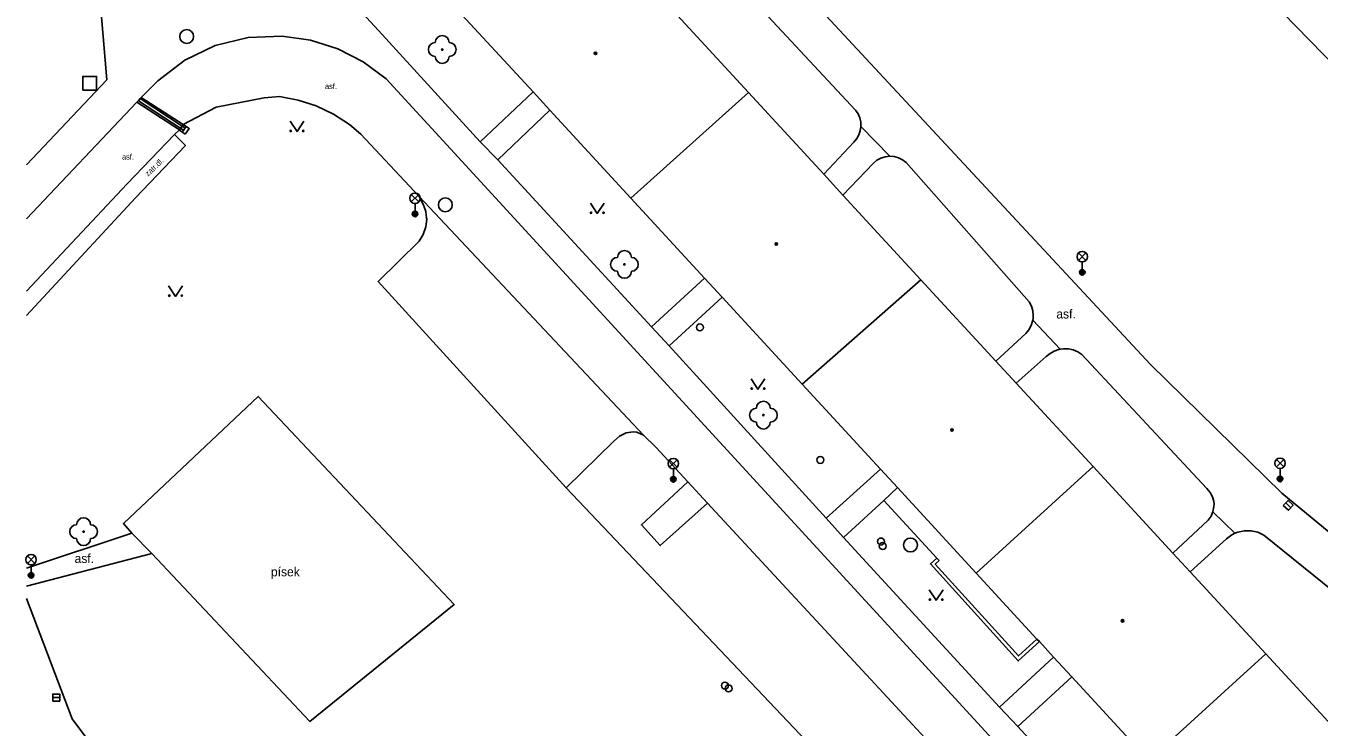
# Model space of a CAD drawing. Extents: x -598932 to -598196, y -1162207 to -1161504.
# Drawn here: x -598932.1 to -598839, y -1161892.2 to -1161841.7 of the extents above; entities that cross this region are included whole.
import ezdxf

# ---------------------------------------------------------------- set-up
doc = ezdxf.new("R2010")
doc.units = 0
for name, color, linetype in [('kanalizace - povrch.  znaky - skut. velikost', 7, 'Continuous'), ('Level 22', 7, 'Continuous'), ('Level 26', 7, 'Continuous'), ('Level 27', 7, 'Continuous'), ('Level 28', 7, 'Continuous'), ('Level 33', 7, 'Continuous'), ('Level 36', 7, 'Continuous'), ('Level 39', 7, 'Continuous'), ('specificka linie pasportu komunikaci', 7, 'Continuous'), ('TM - budovy zdene_ betonove - VP', 7, 'Continuous'), ('TM - chodniky - VP', 7, 'Continuous'), ('TM - komunikace - VP', 7, 'Continuous'), ('TM - letecke snimky - pomocna linie', 7, 'Continuous'), ('TM - popis povrchu', 7, 'Continuous'), ('TM - rozhrani mezi zpev. plochami mezi sebou - VP', 7, 'Continuous'), ('TM - rozhrani ploch obecne - VP', 7, 'Continuous')]:
    doc.layers.add(name, color=color, linetype=linetype)

msp = doc.modelspace()

# ---------------------------------------------------------------- linework, layer by layer
at = {"layer": 'kanalizace - povrch.  znaky - skut. velikost'}
for points in [[(-598923.95, -1161847.12), (-598923.84, -1161846.95)], [(-598920.92, -1161849.1), (-598923.95, -1161847.12)], [(-598920.81, -1161848.93), (-598923.84, -1161846.95)], [(-598920.72, -1161849.23), (-598920.92, -1161849.1)], [(-598920.61, -1161849.06), (-598920.81, -1161848.93)], [(-598920.72, -1161849.23), (-598920.61, -1161849.06)]]:
    msp.add_lwpolyline(points, dxfattribs=at)
at = {"layer": 'Level 22'}
for centre in [(-598902.1, -1161843.43), (-598888.99, -1161858.88), (-598878.99, -1161869.72), (-598927.91, -1161878.1)]:
    msp.add_circle(centre, 0.05, dxfattribs=at)
for centre, start, end in [((-598902.6, -1161843.43), 90, 270), ((-598902.1, -1161842.93), 0, 180), ((-598901.6, -1161843.43), 270, 90), ((-598902.1, -1161843.93), 180, 0), ((-598888.99, -1161858.38), 0, 180), ((-598889.49, -1161858.88), 90, 270), ((-598888.49, -1161858.88), 270, 90), ((-598888.99, -1161859.38), 180, 0), ((-598878.99, -1161869.22), 0, 180), ((-598879.49, -1161869.72), 90, 270), ((-598878.49, -1161869.72), 270, 90), ((-598878.99, -1161870.22), 180, 0), ((-598927.91, -1161877.6), 0, 180), ((-598928.41, -1161878.1), 90, 270), ((-598927.41, -1161878.1), 270, 90), ((-598927.91, -1161878.6), 180, 0)]:
    msp.add_arc(centre, 0.5, start, end, dxfattribs=at)
at = {"layer": 'Level 26'}
msp.add_lwpolyline([(-598927.97, -1161846.36), (-598926.97, -1161846.36), (-598926.97, -1161845.36), (-598927.97, -1161845.36)], close=True, dxfattribs=at)
at = {"layer": 'Level 27'}
for p, q in [((-598920.813, -1161849.375), (-598920.527, -1161848.965)), ((-598841.401, -1161876.038), (-598841.038, -1161876.382)), ((-598930.13, -1161890.03), (-598929.63, -1161890.03))]:
    msp.add_line(p, q, dxfattribs=at)
for points in [[(-598920.607, -1161849.518), (-598920.322, -1161849.107), (-598920.733, -1161848.822), (-598921.018, -1161849.233)], [(-598841.573, -1161876.22), (-598841.21, -1161876.563), (-598840.866, -1161876.2), (-598841.229, -1161875.857)], [(-598930.13, -1161890.28), (-598929.63, -1161890.28), (-598929.63, -1161889.78), (-598930.13, -1161889.78)]]:
    msp.add_lwpolyline(points, close=True, dxfattribs=at)
for centre in [(-598920.49, -1161842.49), (-598901.88, -1161854.6), (-598868.4, -1161879.06)]:
    msp.add_circle(centre, 0.5, dxfattribs=at)
at = {"layer": 'Level 28'}
for centre in [(-598883.56, -1161863.41), (-598874.89, -1161872.94), (-598870.53, -1161878.81), (-598870.4, -1161879.14), (-598881.76, -1161889.17), (-598881.49, -1161889.37)]:
    msp.add_circle(centre, 0.25, dxfattribs=at)
at = {"layer": 'Level 33'}
for p, q in [((-598904.325, -1161854.39), (-598903.795, -1161853.86)), ((-598904.325, -1161853.86), (-598903.795, -1161854.39)), ((-598904.06, -1161854.5), (-598904.06, -1161855.25)), ((-598856.305, -1161858.59), (-598855.775, -1161858.06)), ((-598856.305, -1161858.06), (-598855.775, -1161858.59)), ((-598856.04, -1161858.7), (-598856.04, -1161859.45)), ((-598885.735, -1161873.47), (-598885.205, -1161872.94)), ((-598885.735, -1161872.94), (-598885.205, -1161873.47)), ((-598885.47, -1161873.58), (-598885.47, -1161874.33)), ((-598842.075, -1161873.45), (-598841.545, -1161872.92)), ((-598842.075, -1161872.92), (-598841.545, -1161873.45)), ((-598841.81, -1161873.56), (-598841.81, -1161874.31)), ((-598931.955, -1161880.38), (-598931.425, -1161879.85)), ((-598931.955, -1161879.85), (-598931.425, -1161880.38)), ((-598931.69, -1161880.49), (-598931.69, -1161881.24))]:
    msp.add_line(p, q, dxfattribs=at)
for centre, radius in [((-598904.06, -1161854.125), 0.375), ((-598904.06, -1161855.25), 0.2), ((-598904.06, -1161855.25), 0.145), ((-598904.06, -1161855.25), 0.0876), ((-598856.04, -1161858.325), 0.375), ((-598856.04, -1161859.45), 0.2), ((-598856.04, -1161859.45), 0.145), ((-598856.04, -1161859.45), 0.0876), ((-598885.47, -1161873.205), 0.375), ((-598841.81, -1161873.185), 0.375), ((-598885.47, -1161874.33), 0.2), ((-598885.47, -1161874.33), 0.145), ((-598885.47, -1161874.33), 0.0876), ((-598841.81, -1161874.31), 0.2), ((-598841.81, -1161874.31), 0.145), ((-598841.81, -1161874.31), 0.0876), ((-598931.69, -1161880.115), 0.375), ((-598931.69, -1161881.24), 0.2), ((-598931.69, -1161881.24), 0.145), ((-598931.69, -1161881.24), 0.0876)]:
    msp.add_circle(centre, radius, dxfattribs=at)
at = {"layer": 'Level 36'}
for points in [[(-598913.05, -1161848.58), (-598912.55, -1161849.33), (-598912.05, -1161848.58)], [(-598891.44, -1161854.47), (-598890.94, -1161855.22), (-598890.44, -1161854.47)], [(-598921.79, -1161860.43), (-598921.29, -1161861.18), (-598920.79, -1161860.43)], [(-598879.88, -1161867.11), (-598879.38, -1161867.86), (-598878.88, -1161867.11)], [(-598867.06, -1161882.28), (-598866.56, -1161883.03), (-598866.06, -1161882.28)]]:
    msp.add_lwpolyline(points, dxfattribs=at)
for centre in [(-598913, -1161849.28), (-598912.101, -1161849.28), (-598891.39, -1161855.17), (-598890.491, -1161855.17), (-598921.74, -1161861.13), (-598920.841, -1161861.13), (-598879.83, -1161867.81), (-598878.931, -1161867.81), (-598867.01, -1161882.98), (-598866.111, -1161882.98)]:
    msp.add_circle(centre, 0.05, dxfattribs=at)
at = {"layer": 'Level 39'}
for centre, radius in [((-598891.07, -1161843.7), 0.09), ((-598891.07, -1161843.7), 0.0398), ((-598878.06, -1161857.42), 0.09), ((-598878.06, -1161857.42), 0.0398), ((-598865.42, -1161870.79), 0.09), ((-598865.42, -1161870.79), 0.0398), ((-598853.14, -1161884.51), 0.09), ((-598853.14, -1161884.51), 0.0398)]:
    msp.add_circle(centre, radius, dxfattribs=at)
at = {"layer": 'specificka linie pasportu komunikaci'}
for points in [[(-598869.9, -1161851.1), (-598871.97, -1161848.96)], [(-598899.36, -1161850.06), (-598898.1, -1161851.36)], [(-598887.61, -1161871.17), (-598903.77, -1161854.01)], [(-598887.03, -1161863.37), (-598885.76, -1161864.74)], [(-598857.616, -1161864.984), (-598857.62, -1161864.98), (-598859.598, -1161862.898)], [(-598883, -1161876.05), (-598886.413, -1161879.096), (-598887.768, -1161877.618), (-598884.42, -1161874.52)], [(-598870.33, -1161875.86), (-598869.33, -1161874.93)], [(-598874.47, -1161877.13), (-598873.22, -1161878.51)], [(-598845.05, -1161878.22), (-598846.64, -1161876.68)], [(-598862, -1161890.72), (-598860.69, -1161892.12)]]:
    msp.add_lwpolyline(points, dxfattribs=at)
at = {"layer": 'TM - budovy zdene_ betonove - VP'}
for points in [[(-598895.56, -1161846.48), (-598901.28, -1161840.28)], [(-598885.74, -1161840.37), (-598880.07, -1161846.52)], [(-598894.35, -1161847.8), (-598895.56, -1161846.48)], [(-598888.53, -1161854.11), (-598880.07, -1161846.52)], [(-598880.07, -1161846.52), (-598874.64, -1161852.4)], [(-598888.53, -1161854.11), (-598894.35, -1161847.8)], [(-598874.64, -1161852.4), (-598873.26, -1161853.9)], [(-598883.23, -1161859.86), (-598888.53, -1161854.11)], [(-598873.26, -1161853.9), (-598867.66, -1161859.98)], [(-598881.96, -1161861.24), (-598883.23, -1161859.86)], [(-598876.19, -1161867.5), (-598867.66, -1161859.98)], [(-598867.66, -1161859.98), (-598862.26, -1161865.83)], [(-598876.19, -1161867.5), (-598881.96, -1161861.24)], [(-598862.26, -1161865.83), (-598860.8, -1161867.42)], [(-598870.55, -1161873.61), (-598876.19, -1161867.5)], [(-598860.8, -1161867.42), (-598855.26, -1161873.42)], [(-598863.67, -1161881.08), (-598869.33, -1161874.93), (-598870.55, -1161873.61)], [(-598863.67, -1161881.08), (-598855.26, -1161873.42)], [(-598855.26, -1161873.42), (-598849.52, -1161879.64)], [(-598849.52, -1161879.64), (-598848.28, -1161880.99)], [(-598859.3, -1161885.82), (-598863.67, -1161881.08)], [(-598848.28, -1161880.99), (-598842.84, -1161886.89)], [(-598859.13, -1161886), (-598859.3, -1161885.82)], [(-598858.1, -1161887.12), (-598859.13, -1161886)], [(-598856.8, -1161888.53), (-598858.1, -1161887.12)], [(-598844.96, -1161888.82), (-598842.84, -1161886.89)], [(-598842.84, -1161886.89), (-598837.25, -1161892.95)], [(-598851.24, -1161894.56), (-598856.8, -1161888.53)], [(-598844.96, -1161888.82), (-598851.24, -1161894.56)]]:
    msp.add_lwpolyline(points, dxfattribs=at)
at = {"layer": 'TM - chodniky - VP'}
for points in [[(-598867.84, -1161813.9), (-598809.56, -1161873.6), (-598820.89, -1161890.44), (-598832.15, -1161883.16), (-598841.68, -1161875.32), (-598851.13, -1161866.08), (-598878.95, -1161836.17), (-598885.26, -1161828.7), (-598885.4, -1161826.42), (-598876.78, -1161822.62), (-598867.84, -1161813.9)], [(-598899.36, -1161850.06), (-598906.43, -1161842.36), (-598911.98, -1161836.28)], [(-598872.35, -1161847.79), (-598880.98, -1161838.53)], [(-598926.24, -1161845.61), (-598926.62, -1161841.08)], [(-598932.017, -1161851.717), (-598926.24, -1161845.61)], [(-598895.56, -1161846.48), (-598899.36, -1161850.06)], [(-598894.35, -1161847.8), (-598898.1, -1161851.36), (-598887.03, -1161863.37), (-598883.23, -1161859.86)], [(-598872.35, -1161847.79), (-598872.176, -1161848.051), (-598872.052, -1161848.339), (-598871.982, -1161848.645), (-598871.97, -1161848.96), (-598872.015, -1161849.269), (-598872.116, -1161849.565), (-598872.269, -1161849.839), (-598872.47, -1161850.08)], [(-598921.37, -1161849.55), (-598920.58, -1161850.33), (-598924.17, -1161854.1)], [(-598874.64, -1161852.4), (-598872.47, -1161850.08)], [(-598871.07, -1161851.59), (-598870.819, -1161851.385), (-598870.533, -1161851.231), (-598870.223, -1161851.135), (-598869.9, -1161851.1), (-598869.578, -1161851.127), (-598869.266, -1161851.215), (-598868.976, -1161851.361), (-598868.72, -1161851.56)], [(-598871.07, -1161851.59), (-598873.26, -1161853.9)], [(-598859.87, -1161861.58), (-598868.72, -1161851.56)], [(-598881.96, -1161861.24), (-598885.76, -1161864.74), (-598874.47, -1161877.13), (-598870.55, -1161873.61)], [(-598859.87, -1161861.58), (-598859.704, -1161861.892), (-598859.603, -1161862.23), (-598859.57, -1161862.582), (-598859.58, -1161862.76), (-598859.598, -1161862.898), (-598859.713, -1161863.27), (-598859.883, -1161863.58), (-598860.11, -1161863.85)], [(-598862.26, -1161865.83), (-598860.11, -1161863.85)], [(-598858.63, -1161865.5), (-598858.359, -1161865.28), (-598858.053, -1161865.111), (-598857.722, -1161865), (-598857.616, -1161864.984), (-598857.38, -1161864.95), (-598857.027, -1161864.962), (-598856.686, -1161865.036), (-598856.363, -1161865.17), (-598856.07, -1161865.36)], [(-598847.07, -1161875), (-598856.07, -1161865.36)], [(-598858.63, -1161865.5), (-598860.8, -1161867.42)], [(-598924.43, -1161878.22), (-598925.04, -1161877.52), (-598915.34, -1161868.38), (-598901.25, -1161883.34), (-598911.64, -1161891.74), (-598922.99, -1161879.67)], [(-598847.07, -1161875), (-598846.838, -1161875.273), (-598846.671, -1161875.59), (-598846.578, -1161875.936), (-598846.56, -1161876.11), (-598846.562, -1161876.294), (-598846.64, -1161876.68), (-598846.763, -1161876.978), (-598846.97, -1161877.27)], [(-598866.51, -1161880), (-598870.33, -1161875.86), (-598873.22, -1161878.51), (-598862, -1161890.72), (-598858.1, -1161887.12)], [(-598849.52, -1161879.64), (-598846.97, -1161877.27)], [(-598932.017, -1161880.721), (-598924.43, -1161878.22)], [(-598845.67, -1161878.62), (-598845.281, -1161878.335), (-598845.05, -1161878.22), (-598844.841, -1161878.139), (-598844.37, -1161878.04), (-598843.888, -1161878.043), (-598843.418, -1161878.148), (-598842.98, -1161878.35)], [(-598833.04, -1161886.35), (-598842.98, -1161878.35)], [(-598845.67, -1161878.62), (-598848.28, -1161880.99)], [(-598922.99, -1161879.67), (-598932.017, -1161882.009)], [(-598859.3, -1161885.82), (-598860.63, -1161887.04), (-598866.62, -1161880.44), (-598866.34, -1161880.18)], [(-598866.34, -1161880.18), (-598866.51, -1161880)], [(-598856.8, -1161888.53), (-598860.69, -1161892.12), (-598849.57, -1161904.24), (-598845.64, -1161900.64)]]:
    msp.add_lwpolyline(points, dxfattribs=at)
at = {"layer": 'TM - komunikace - VP'}
for points in [[(-598922.57, -1161845.67), (-598920.63, -1161844.19), (-598918.43, -1161843.14), (-598916.06, -1161842.56)], [(-598916.06, -1161842.56), (-598913.62, -1161842.47)], [(-598913.62, -1161842.47), (-598911.58, -1161842.75), (-598909.62, -1161843.37), (-598907.79, -1161844.31), (-598906.14, -1161845.54)], [(-598932.017, -1161855.598), (-598924.07, -1161847.21), (-598923.84, -1161846.95), (-598923.76, -1161846.87), (-598922.57, -1161845.67)], [(-598906.14, -1161845.54), (-598900.7, -1161851.45)], [(-598914.91, -1161846.9), (-598918.37, -1161847.58), (-598920.75, -1161848.83), (-598920.81, -1161848.93)], [(-598914.91, -1161846.9), (-598913.81, -1161846.8)], [(-598913.81, -1161846.8), (-598912.47, -1161847.06), (-598911.17, -1161847.49), (-598909.93, -1161848.07), (-598908.78, -1161848.81)], [(-598920.92, -1161849.1), (-598921, -1161849.21), (-598921.37, -1161849.55), (-598924.78, -1161853.08)], [(-598920.81, -1161848.93), (-598920.92, -1161849.1)], [(-598908.78, -1161848.81), (-598907.97, -1161849.51), (-598903.77, -1161854.01)], [(-598900.7, -1161851.45), (-598847.71, -1161909.14)], [(-598932.017, -1161860.799), (-598924.78, -1161853.08)], [(-598903.77, -1161854.01), (-598903.464, -1161854.539), (-598903.281, -1161855.072), (-598903.227, -1161855.565), (-598903.22, -1161855.63), (-598903.284, -1161856.191), (-598903.471, -1161856.723), (-598903.77, -1161857.2)], [(-598903.77, -1161857.2), (-598906.72, -1161860.1), (-598893.18, -1161874.95)], [(-598889.74, -1161871.59), (-598889.352, -1161871.229), (-598888.875, -1161870.999), (-598888.352, -1161870.92), (-598888.09, -1161870.94), (-598887.613, -1161871.17), (-598886.7, -1161872.05)], [(-598893.18, -1161874.95), (-598889.74, -1161871.59)], [(-598886.7, -1161872.05), (-598884.42, -1161874.52), (-598883, -1161876.05), (-598866.47, -1161893.92), (-598865.03, -1161895.48), (-598853.37, -1161908.08)], [(-598932.017, -1161882.918), (-598928.74, -1161891.57)], [(-598901.12, -1161928.35), (-598907.8, -1161919.4), (-598915.24, -1161909.5), (-598916.41, -1161907.97), (-598921.64, -1161901.03), (-598928.74, -1161891.57)]]:
    msp.add_lwpolyline(points, dxfattribs=at)
at = {"layer": 'TM - letecke snimky - pomocna linie'}
msp.add_lwpolyline([(-598924.17, -1161854.1), (-598932.017, -1161862.55)], dxfattribs=at)
at = {"layer": 'TM - rozhrani mezi zpev. plochami mezi sebou - VP'}
for points in [[(-598893.18, -1161874.95), (-598857.74, -1161912.28)], [(-598922.99, -1161879.67), (-598924.43, -1161878.22)]]:
    msp.add_lwpolyline(points, dxfattribs=at)
at = {"layer": 'TM - rozhrani ploch obecne - VP'}
for points in [[(-598921, -1161849.21), (-598924.07, -1161847.21)], [(-598923.76, -1161846.87), (-598920.75, -1161848.83)], [(-598859.13, -1161886), (-598860.65, -1161887.39), (-598866.97, -1161880.42), (-598866.51, -1161880)]]:
    msp.add_lwpolyline(points, dxfattribs=at)

# ---------------------------------------------------------------- texts
at = {"layer": 'TM - popis povrchu'}
for s, height, p in [('asf.', 0.4, (-598910.54, -1161846.27)), ('asf.', 0.4, (-598925.15, -1161851.34)), ('asf.', 0.65, (-598857.91, -1161862.77)), ('asf.', 0.65, (-598928.56, -1161880.35)), ('písek', 0.65, (-598914.43, -1161881.31))]:
    msp.add_text(s, height=height, dxfattribs=at).set_placement(p)
msp.add_text('zatr.dl.', height=0.4, rotation=43.4302, dxfattribs=at).set_placement((-598923.27, -1161852.58))

doc.saveas('drawing.dxf')
